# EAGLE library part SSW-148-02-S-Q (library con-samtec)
THROUGH-HOLE .025" SQ POST SOCKET Source: Samtec SSW.pdf
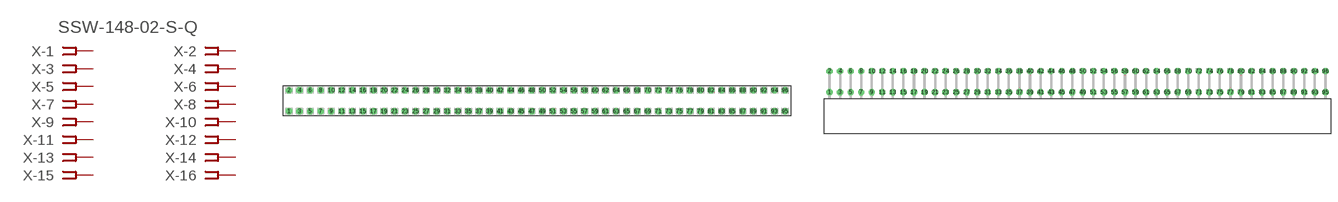
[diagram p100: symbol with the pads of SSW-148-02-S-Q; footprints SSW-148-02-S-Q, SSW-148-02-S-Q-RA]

Designator prefix X; gates -1=FPINV -2=FPIN -3=FPIN -4=FPIN -5=FPIN -6=FPIN -7=FPIN -8=FPIN -9=FPIN -10=FPIN -11=FPIN -12=FPIN -13=FPIN -14=FPIN -15=FPIN -16=FPIN -17=FPIN -18=FPIN -19=FPIN -20=FPIN -21=FPIN -22=FPIN -23=FPIN -24=FPIN -25=FPIN -26=FPIN -27=FPIN -28=FPIN -29=FPIN -30=FPIN -31=FPIN -32=FPIN -33=FPIN -34=FPIN -35=FPIN -36=FPIN -37=FPIN -38=FPIN -39=FPIN -40=FPIN -41=FPIN -42=FPIN -43=FPIN -44=FPIN -45=FPIN -46=FPIN -47=FPIN -48=FPIN -49=FPIN -50=FPIN -51=FPIN -52=FPIN -53=FPIN -54=FPIN -55=FPIN -56=FPIN -57=FPIN -58=FPIN -59=FPIN -60=FPIN -61=FPIN -62=FPIN -63=FPIN -64=FPIN -65=FPIN -66=FPIN -67=FPIN -68=FPIN -69=FPIN -70=FPIN -71=FPIN -72=FPIN -73=FPIN -74=FPIN -75=FPIN -76=FPIN -77=FPIN -78=FPIN -79=FPIN -80=FPIN -81=FPIN -82=FPIN -83=FPIN -84=FPIN -85=FPIN -86=FPIN -87=FPIN -88=FPIN -89=FPIN -90=FPIN -91=FPIN -92=FPIN -93=FPIN -94=FPIN -95=FPIN -96=FPIN

## SSW-148-02-S-Q (MPN: SSW-148-02-S-Q; OC_FARNELL: unknown; OC_NEWARK: 83P1710)  [SSW-148-02-S-Q]
1  -1:1  pas
2  -2:1  pas
3  -3:1  pas
4  -4:1  pas
5  -5:1  pas
6  -6:1  pas
7  -7:1  pas
8  -8:1  pas
9  -9:1  pas
10  -10:1  pas
11  -11:1  pas
12  -12:1  pas
13  -13:1  pas
14  -14:1  pas
15  -15:1  pas
16  -16:1  pas
17  -17:1  pas
18  -18:1  pas
19  -19:1  pas
20  -20:1  pas
21  -21:1  pas
22  -22:1  pas
23  -23:1  pas
24  -24:1  pas
25  -25:1  pas
26  -26:1  pas
27  -27:1  pas
28  -28:1  pas
29  -29:1  pas
30  -30:1  pas
31  -31:1  pas
32  -32:1  pas
33  -33:1  pas
34  -34:1  pas
35  -35:1  pas
36  -36:1  pas
37  -37:1  pas
38  -38:1  pas
39  -39:1  pas
40  -40:1  pas
41  -41:1  pas
42  -42:1  pas
43  -43:1  pas
44  -44:1  pas
45  -45:1  pas
46  -46:1  pas
47  -47:1  pas
48  -48:1  pas
49  -49:1  pas
50  -50:1  pas
51  -51:1  pas
52  -52:1  pas
53  -53:1  pas
54  -54:1  pas
55  -55:1  pas
56  -56:1  pas
57  -57:1  pas
58  -58:1  pas
59  -59:1  pas
60  -60:1  pas
61  -61:1  pas
62  -62:1  pas
63  -63:1  pas
64  -64:1  pas
65  -65:1  pas
66  -66:1  pas
67  -67:1  pas
68  -68:1  pas
69  -69:1  pas
70  -70:1  pas
71  -71:1  pas
72  -72:1  pas
73  -73:1  pas
74  -74:1  pas
75  -75:1  pas
76  -76:1  pas
77  -77:1  pas
78  -78:1  pas
79  -79:1  pas
80  -80:1  pas
81  -81:1  pas
82  -82:1  pas
83  -83:1  pas
84  -84:1  pas
85  -85:1  pas
86  -86:1  pas
87  -87:1  pas
88  -88:1  pas
89  -89:1  pas
90  -90:1  pas
91  -91:1  pas
92  -92:1  pas
93  -93:1  pas
94  -94:1  pas
95  -95:1  pas
96  -96:1  pas

## SSW-148-02-S-QRA (MPN: SSW-148-02-S-Q-RA; OC_FARNELL: unknown; OC_NEWARK: 83P1711)  [SSW-148-02-S-Q-RA]
Pads as for SSW-148-02-S-Q

## Footprint SSW-148-02-S-Q (pad centres in mm)
THROUGH-HOLE .025" SQ POST SOCKET Source: Samtec SSW.pdf
drill 1 pad 1.5 octagon: 1 -59.69,-2.54; 2 -59.69,2.54; 3 -57.15,-2.54; 4 -57.15,2.54; 5 -54.61,-2.54; 6 -54.61,2.54; 7 -52.07,-2.54; 8 -52.07,2.54; 9 -49.53,-2.54; 10 -49.53,2.54; 11 -46.99,-2.54; 12 -46.99,2.54; 13 -44.45,-2.54; 14 -44.45,2.54; 15 -41.91,-2.54; 16 -41.91,2.54; 17 -39.37,-2.54; 18 -39.37,2.54; 19 -36.83,-2.54; 20 -36.83,2.54; 21 -34.29,-2.54; 22 -34.29,2.54; 23 -31.75,-2.54; 24 -31.75,2.54; 25 -29.21,-2.54; 26 -29.21,2.54; 27 -26.67,-2.54; 28 -26.67,2.54; 29 -24.13,-2.54; 30 -24.13,2.54; 31 -21.59,-2.54; 32 -21.59,2.54; 33 -19.05,-2.54; 34 -19.05,2.54; 35 -16.51,-2.54; 36 -16.51,2.54; 37 -13.97,-2.54; 38 -13.97,2.54; 39 -11.43,-2.54; 40 -11.43,2.54; 41 -8.89,-2.54; 42 -8.89,2.54; 43 -6.35,-2.54; 44 -6.35,2.54; 45 -3.81,-2.54; 46 -3.81,2.54; 47 -1.27,-2.54; 48 -1.27,2.54; 49 1.27,-2.54; 50 1.27,2.54; 51 3.81,-2.54; 52 3.81,2.54; 53 6.35,-2.54; 54 6.35,2.54; 55 8.89,-2.54; 56 8.89,2.54; 57 11.43,-2.54; 58 11.43,2.54; 59 13.97,-2.54; 60 13.97,2.54; 61 16.51,-2.54; 62 16.51,2.54; 63 19.05,-2.54; 64 19.05,2.54; 65 21.59,-2.54; 66 21.59,2.54; 67 24.13,-2.54; 68 24.13,2.54; 69 26.67,-2.54; 70 26.67,2.54; 71 29.21,-2.54; 72 29.21,2.54; 73 31.75,-2.54; 74 31.75,2.54; 75 34.29,-2.54; 76 34.29,2.54; 77 36.83,-2.54; 78 36.83,2.54; 79 39.37,-2.54; 80 39.37,2.54; 81 41.91,-2.54; 82 41.91,2.54; 83 44.45,-2.54; 84 44.45,2.54; 85 46.99,-2.54; 86 46.99,2.54; 87 49.53,-2.54; 88 49.53,2.54; 89 52.07,-2.54; 90 52.07,2.54; 91 54.61,-2.54; 92 54.61,2.54; 93 57.15,-2.54; 94 57.15,2.54; 95 59.69,-2.54; 96 59.69,2.54

## Footprint SSW-148-02-S-Q-RA (pad centres in mm)
THROUGH-HOLE .025" SQ POST SOCKET Source: Samtec SSW.pdf
drill 1 pad 1.5 octagon: 1 -59.69,1.524; 2 -59.69,6.604; 3 -57.15,1.524; 4 -57.15,6.604; 5 -54.61,1.524; 6 -54.61,6.604; 7 -52.07,1.524; 8 -52.07,6.604; 9 -49.53,1.524; 10 -49.53,6.604; 11 -46.99,1.524; 12 -46.99,6.604; 13 -44.45,1.524; 14 -44.45,6.604; 15 -41.91,1.524; 16 -41.91,6.604; 17 -39.37,1.524; 18 -39.37,6.604; 19 -36.83,1.524; 20 -36.83,6.604; 21 -34.29,1.524; 22 -34.29,6.604; 23 -31.75,1.524; 24 -31.75,6.604; 25 -29.21,1.524; 26 -29.21,6.604; 27 -26.67,1.524; 28 -26.67,6.604; 29 -24.13,1.524; 30 -24.13,6.604; 31 -21.59,1.524; 32 -21.59,6.604; 33 -19.05,1.524; 34 -19.05,6.604; 35 -16.51,1.524; 36 -16.51,6.604; 37 -13.97,1.524; 38 -13.97,6.604; 39 -11.43,1.524; 40 -11.43,6.604; 41 -8.89,1.524; 42 -8.89,6.604; 43 -6.35,1.524; 44 -6.35,6.604; 45 -3.81,1.524; 46 -3.81,6.604; 47 -1.27,1.524; 48 -1.27,6.604; 49 1.27,1.524; 50 1.27,6.604; 51 3.81,1.524; 52 3.81,6.604; 53 6.35,1.524; 54 6.35,6.604; 55 8.89,1.524; 56 8.89,6.604; 57 11.43,1.524; 58 11.43,6.604; 59 13.97,1.524; 60 13.97,6.604; 61 16.51,1.524; 62 16.51,6.604; 63 19.05,1.524; 64 19.05,6.604; 65 21.59,1.524; 66 21.59,6.604; 67 24.13,1.524; 68 24.13,6.604; 69 26.67,1.524; 70 26.67,6.604; 71 29.21,1.524; 72 29.21,6.604; 73 31.75,1.524; 74 31.75,6.604; 75 34.29,1.524; 76 34.29,6.604; 77 36.83,1.524; 78 36.83,6.604; 79 39.37,1.524; 80 39.37,6.604; 81 41.91,1.524; 82 41.91,6.604; 83 44.45,1.524; 84 44.45,6.604; 85 46.99,1.524; 86 46.99,6.604; 87 49.53,1.524; 88 49.53,6.604; 89 52.07,1.524; 90 52.07,6.604; 91 54.61,1.524; 92 54.61,6.604; 93 57.15,1.524; 94 57.15,6.604; 95 59.69,1.524; 96 59.69,6.604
